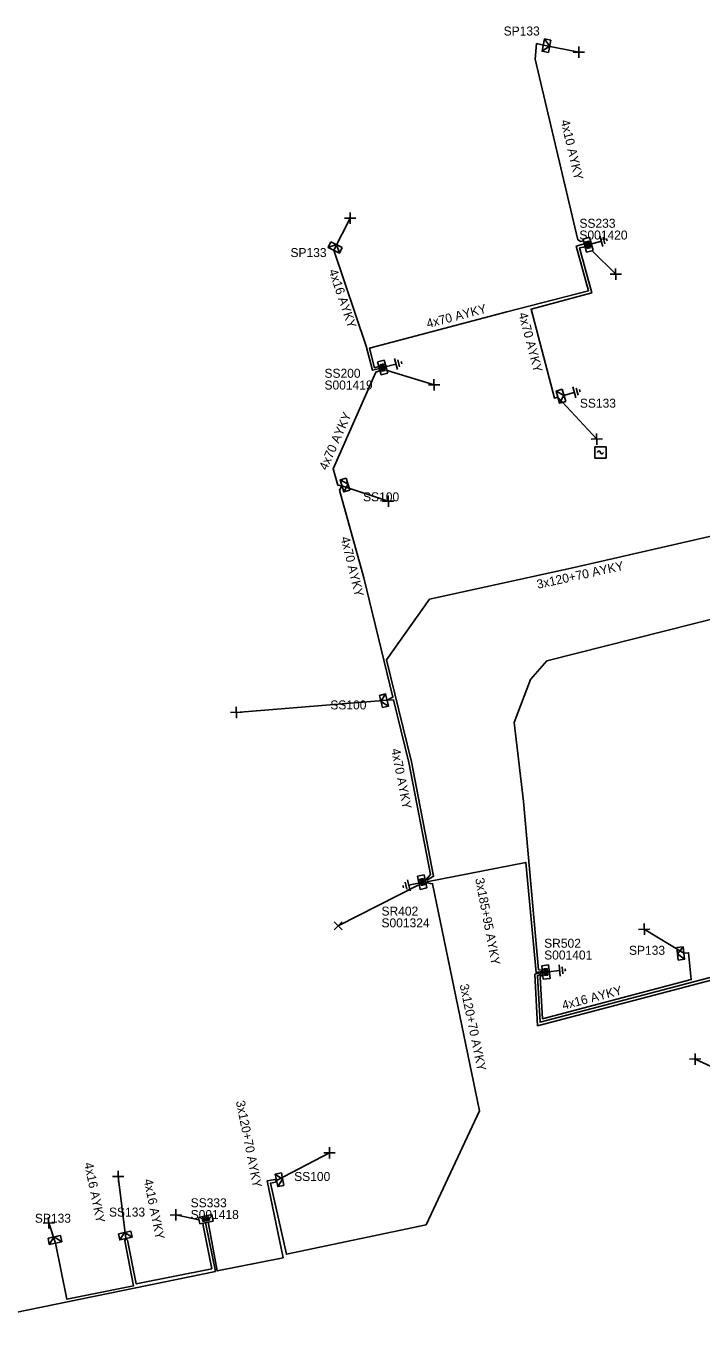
# Model space of a CAD drawing. Extents: x -762500 to -761285, y -1155006 to -1154135.
# Drawn here: x -762371 to -762296.3, y -1154695.7 to -1154549.7 of the extents above; entities that cross this region are included whole.
import ezdxf

# ---------------------------------------------------------------- set-up
doc = ezdxf.new("R2010")
doc.units = 0
for name, color, linetype in [('Vrstva 15', 7, 'Continuous'), ('Vrstva 28', 7, 'Continuous'), ('Vrstva 29', 7, 'Continuous'), ('Vrstva 30', 7, 'Continuous'), ('Vrstva 31', 7, 'Continuous'), ('Vrstva 33', 7, 'Continuous'), ('Vrstva 34', 7, 'Continuous'), ('Vrstva 5', 7, 'Continuous'), ('Vrstva 59', 7, 'Continuous'), ('Vrstva 6', 7, 'Continuous')]:
    doc.layers.add(name, color=color, linetype=linetype)

msp = doc.modelspace()

# ---------------------------------------------------------------- linework, layer by layer
at = {"layer": 'Vrstva 15'}
for points in [[(-762308.583, -1154573.801), (-762307.376, -1154573.477)], [(-762307.537, -1154572.873), (-762307.214, -1154574.081)], [(-762307.176, -1154573.026), (-762306.972, -1154573.787)], [(-762306.806, -1154573.187), (-762306.772, -1154573.315)], [(-762306.772, -1154573.315), (-762306.739, -1154573.439)], [(-762331.302, -1154587.4), (-762330.095, -1154587.076)], [(-762330.257, -1154586.472), (-762329.933, -1154587.68)], [(-762329.895, -1154586.625), (-762329.691, -1154587.386)], [(-762329.526, -1154586.786), (-762329.491, -1154586.914)], [(-762329.491, -1154586.914), (-762329.458, -1154587.038)], [(-762310.537, -1154589.614), (-762310.193, -1154590.816)], [(-762310.173, -1154589.76), (-762309.955, -1154590.517)], [(-762309.801, -1154589.915), (-762309.764, -1154590.042)], [(-762309.764, -1154590.042), (-762309.729, -1154590.166)], [(-762311.566, -1154590.559), (-762310.365, -1154590.215)], [(-762328.53, -1154645.369), (-762328.811, -1154644.151)], [(-762329.279, -1154644.9), (-762329.308, -1154644.776)], [(-762329.249, -1154645.03), (-762329.279, -1154644.9)], [(-762328.886, -1154645.204), (-762329.063, -1154644.436)], [(-762327.452, -1154644.479), (-762328.67, -1154644.76)], [(-762313.234, -1154654.338), (-762311.991, -1154654.208)], [(-762312.056, -1154653.586), (-762311.926, -1154654.829)], [(-762311.723, -1154653.794), (-762311.64, -1154654.577)], [(-762311.383, -1154654.01), (-762311.369, -1154654.142)], [(-762311.369, -1154654.142), (-762311.356, -1154654.27)]]:
    msp.add_lwpolyline(points, dxfattribs=at)
at = {"layer": 'Vrstva 28'}
for points in [[(-762308.673, -1154573.05), (-762309.398, -1154573.244)], [(-762309.398, -1154573.244), (-762309.01, -1154574.693)], [(-762308.757, -1154573.47), (-762309.122, -1154573.567)], [(-762309.122, -1154573.567), (-762308.929, -1154574.286)], [(-762308.79, -1154573.527), (-762309.064, -1154573.601)], [(-762309.064, -1154573.601), (-762308.896, -1154574.228)], [(-762308.823, -1154573.585), (-762309.006, -1154573.634)], [(-762309.006, -1154573.634), (-762308.862, -1154574.17)], [(-762308.857, -1154573.643), (-762308.948, -1154573.668)], [(-762308.948, -1154573.668), (-762308.829, -1154574.113)], [(-762308.794, -1154574.06), (-762308.892, -1154573.695)], [(-762308.738, -1154574.088), (-762308.857, -1154573.643)], [(-762308.829, -1154574.113), (-762308.738, -1154574.088)], [(-762308.68, -1154574.122), (-762308.823, -1154573.585)], [(-762308.622, -1154574.155), (-762308.79, -1154573.527)], [(-762308.564, -1154574.188), (-762308.757, -1154573.47)], [(-762308.285, -1154574.499), (-762308.673, -1154573.05)], [(-762309.01, -1154574.693), (-762308.285, -1154574.499)], [(-762308.929, -1154574.286), (-762308.564, -1154574.188)], [(-762308.896, -1154574.228), (-762308.622, -1154574.155)], [(-762308.862, -1154574.17), (-762308.68, -1154574.122)], [(-762331.41, -1154586.641), (-762332.131, -1154586.848)], [(-762332.131, -1154586.848), (-762331.718, -1154588.29)], [(-762331.486, -1154587.062), (-762331.849, -1154587.166)], [(-762331.849, -1154587.166), (-762331.644, -1154587.882)], [(-762331.518, -1154587.121), (-762331.791, -1154587.199)], [(-762331.791, -1154587.199), (-762331.612, -1154587.823)], [(-762331.551, -1154587.179), (-762331.732, -1154587.231)], [(-762331.732, -1154587.231), (-762331.579, -1154587.765)], [(-762331.398, -1154587.713), (-762331.551, -1154587.179)], [(-762331.339, -1154587.745), (-762331.518, -1154587.121)], [(-762331.281, -1154587.777), (-762331.486, -1154587.062)], [(-762330.997, -1154588.083), (-762331.41, -1154586.641)], [(-762331.718, -1154588.29), (-762330.997, -1154588.083)], [(-762331.583, -1154587.237), (-762331.674, -1154587.264)], [(-762331.674, -1154587.264), (-762331.547, -1154587.706)], [(-762331.644, -1154587.882), (-762331.281, -1154587.777)], [(-762331.513, -1154587.654), (-762331.617, -1154587.29)], [(-762331.612, -1154587.823), (-762331.339, -1154587.745)], [(-762331.456, -1154587.68), (-762331.583, -1154587.237)], [(-762331.579, -1154587.765), (-762331.398, -1154587.713)], [(-762331.547, -1154587.706), (-762331.456, -1154587.68)], [(-762326.982, -1154643.598), (-762327.715, -1154643.754)], [(-762327.715, -1154643.754), (-762327.403, -1154645.221)], [(-762327.083, -1154644), (-762327.453, -1154644.078)], [(-762327.453, -1154644.078), (-762327.298, -1154644.806)], [(-762327.12, -1154644.056), (-762327.397, -1154644.115)], [(-762327.397, -1154644.115), (-762327.262, -1154644.75)], [(-762327.156, -1154644.112), (-762327.341, -1154644.151)], [(-762327.341, -1154644.151), (-762327.226, -1154644.694)], [(-762327.193, -1154644.168), (-762327.285, -1154644.187)], [(-762327.097, -1154644.618), (-762327.193, -1154644.168)], [(-762327.041, -1154644.655), (-762327.156, -1154644.112)], [(-762326.985, -1154644.691), (-762327.12, -1154644.056)], [(-762326.929, -1154644.728), (-762327.083, -1154644)], [(-762326.67, -1154645.065), (-762326.982, -1154643.598)], [(-762327.403, -1154645.221), (-762326.67, -1154645.065)], [(-762327.298, -1154644.806), (-762326.929, -1154644.728)], [(-762327.285, -1154644.187), (-762327.189, -1154644.638)], [(-762327.262, -1154644.75), (-762326.985, -1154644.691)], [(-762327.23, -1154644.218), (-762327.152, -1154644.588)], [(-762327.226, -1154644.694), (-762327.041, -1154644.655)], [(-762327.189, -1154644.638), (-762327.097, -1154644.618)], [(-762313.206, -1154653.584), (-762313.952, -1154653.662)], [(-762313.952, -1154653.662), (-762313.795, -1154655.154)], [(-762313.354, -1154653.985), (-762313.73, -1154654.025)], [(-762313.73, -1154654.025), (-762313.652, -1154654.765)], [(-762313.396, -1154654.037), (-762313.678, -1154654.067)], [(-762313.678, -1154654.067), (-762313.61, -1154654.713)], [(-762313.438, -1154654.089), (-762313.626, -1154654.109)], [(-762313.626, -1154654.109), (-762313.568, -1154654.661)], [(-762313.48, -1154654.141), (-762313.574, -1154654.151)], [(-762313.574, -1154654.151), (-762313.526, -1154654.609)], [(-762313.483, -1154654.563), (-762313.523, -1154654.187)], [(-762313.432, -1154654.599), (-762313.48, -1154654.141)], [(-762313.38, -1154654.641), (-762313.438, -1154654.089)], [(-762313.328, -1154654.683), (-762313.396, -1154654.037)], [(-762313.276, -1154654.725), (-762313.354, -1154653.985)], [(-762313.049, -1154655.076), (-762313.206, -1154653.584)], [(-762313.795, -1154655.154), (-762313.049, -1154655.076)], [(-762313.652, -1154654.765), (-762313.276, -1154654.725)], [(-762313.61, -1154654.713), (-762313.328, -1154654.683)], [(-762313.568, -1154654.661), (-762313.38, -1154654.641)], [(-762313.526, -1154654.609), (-762313.432, -1154654.599)], [(-762350.473, -1154681.204), (-762351.941, -1154681.516)], [(-762351.941, -1154681.516), (-762351.785, -1154682.25)], [(-762351.785, -1154682.25), (-762350.317, -1154681.938)], [(-762350.798, -1154681.467), (-762351.526, -1154681.621)], [(-762351.526, -1154681.621), (-762351.447, -1154681.991)], [(-762350.834, -1154681.523), (-762351.47, -1154681.658)], [(-762351.47, -1154681.658), (-762351.411, -1154681.935)], [(-762351.447, -1154681.991), (-762350.72, -1154681.836)], [(-762350.871, -1154681.579), (-762351.414, -1154681.694)], [(-762351.414, -1154681.694), (-762351.375, -1154681.879)], [(-762351.411, -1154681.935), (-762350.776, -1154681.8)], [(-762351.375, -1154681.879), (-762350.832, -1154681.763)], [(-762350.907, -1154681.635), (-762351.358, -1154681.73)], [(-762351.358, -1154681.73), (-762351.338, -1154681.823)], [(-762351.338, -1154681.823), (-762350.888, -1154681.727)], [(-762350.938, -1154681.689), (-762351.308, -1154681.768)], [(-762350.888, -1154681.727), (-762350.907, -1154681.635)], [(-762350.832, -1154681.763), (-762350.871, -1154681.579)], [(-762350.776, -1154681.8), (-762350.834, -1154681.523)], [(-762350.72, -1154681.836), (-762350.798, -1154681.467)], [(-762350.317, -1154681.938), (-762350.473, -1154681.204)]]:
    msp.add_lwpolyline(points, dxfattribs=at)
at = {"layer": 'Vrstva 31'}
for points in [[(-762313.237, -1154552.604), (-762313.924, -1154552.47), (-762313.657, -1154551.096), (-762312.97, -1154551.23)], [(-762313.103, -1154551.917), (-762313.924, -1154552.47)], [(-762313.103, -1154551.917), (-762313.657, -1154551.096)], [(-762313.237, -1154552.604), (-762312.97, -1154551.23)], [(-762336.036, -1154574.185), (-762336.354, -1154574.809), (-762337.601, -1154574.173), (-762337.283, -1154573.549)], [(-762336.659, -1154573.867), (-762337.601, -1154574.173)], [(-762336.036, -1154574.185), (-762337.283, -1154573.549)], [(-762336.659, -1154573.867), (-762336.354, -1154574.809)], [(-762311.313, -1154591.223), (-762311.986, -1154591.416), (-762312.372, -1154590.07), (-762311.699, -1154589.877)], [(-762311.506, -1154590.55), (-762312.372, -1154590.07)], [(-762311.313, -1154591.223), (-762311.699, -1154589.877)], [(-762311.506, -1154590.55), (-762311.986, -1154591.416)], [(-762335.203, -1154601.043), (-762335.876, -1154601.236), (-762336.261, -1154599.89), (-762335.589, -1154599.697)], [(-762335.396, -1154600.37), (-762336.261, -1154599.89)], [(-762335.396, -1154600.37), (-762335.876, -1154601.236)], [(-762335.203, -1154601.043), (-762335.589, -1154599.697)], [(-762331.92, -1154623.748), (-762331.241, -1154623.578), (-762330.902, -1154624.937), (-762331.581, -1154625.106)], [(-762331.751, -1154624.427), (-762331.241, -1154623.578)], [(-762331.92, -1154623.748), (-762331.581, -1154625.106)], [(-762331.751, -1154624.427), (-762330.902, -1154624.937)], [(-762299.031, -1154651.647), (-762298.336, -1154651.562), (-762298.165, -1154652.952), (-762298.86, -1154653.037)], [(-762299.031, -1154651.647), (-762298.86, -1154653.037)], [(-762298.945, -1154652.342), (-762298.336, -1154651.562)], [(-762298.945, -1154652.342), (-762298.165, -1154652.952)], [(-762342.479, -1154677.972), (-762343.164, -1154678.117), (-762343.455, -1154676.748), (-762342.77, -1154676.602)], [(-762342.625, -1154677.287), (-762343.455, -1154676.748)], [(-762342.625, -1154677.287), (-762343.164, -1154678.117)], [(-762342.479, -1154677.972), (-762342.77, -1154676.602)], [(-762367.209, -1154683.539), (-762368.578, -1154683.83)], [(-762367.209, -1154683.539), (-762367.063, -1154684.224), (-762368.432, -1154684.515), (-762368.578, -1154683.83)], [(-762359.428, -1154683.039), (-762360.797, -1154683.33)], [(-762359.428, -1154683.039), (-762359.282, -1154683.723), (-762360.652, -1154684.014), (-762360.797, -1154683.33)], [(-762360.112, -1154683.184), (-762360.652, -1154684.014)], [(-762360.112, -1154683.184), (-762359.282, -1154683.723)], [(-762367.893, -1154683.685), (-762368.432, -1154684.515)], [(-762367.893, -1154683.685), (-762367.063, -1154684.224)]]:
    msp.add_lwpolyline(points, dxfattribs=at)
at = {"layer": 'Vrstva 34'}
for points in [[(-762309.859, -1154553.195), (-762309.881, -1154551.945)], [(-762310.495, -1154552.581), (-762309.245, -1154552.559)], [(-762335.775, -1154570.941), (-762334.525, -1154570.919)], [(-762335.139, -1154571.555), (-762335.161, -1154570.305)], [(-762305.769, -1154577.755), (-762305.791, -1154576.505)], [(-762306.405, -1154577.141), (-762305.155, -1154577.119)], [(-762326.505, -1154589.391), (-762325.255, -1154589.369)], [(-762325.869, -1154590.005), (-762325.891, -1154588.755)], [(-762308.515, -1154595.391), (-762307.265, -1154595.369)], [(-762307.879, -1154596.005), (-762307.901, -1154594.755)], [(-762306.856, -1154596.236), (-762308.106, -1154596.236)], [(-762308.106, -1154596.236), (-762308.106, -1154597.486)], [(-762307.481, -1154596.861), (-762307.482, -1154596.845), (-762307.484, -1154596.83), (-762307.488, -1154596.814), (-762307.494, -1154596.799), (-762307.501, -1154596.785), (-762307.51, -1154596.772), (-762307.52, -1154596.759), (-762307.531, -1154596.748), (-762307.543, -1154596.738), (-762307.557, -1154596.729), (-762307.571, -1154596.721), (-762307.586, -1154596.716), (-762307.601, -1154596.712), (-762307.617, -1154596.709), (-762307.633, -1154596.708), (-762307.649, -1154596.709), (-762307.665, -1154596.711), (-762307.68, -1154596.715), (-762307.695, -1154596.721), (-762307.709, -1154596.728), (-762307.723, -1154596.737), (-762307.735, -1154596.747), (-762307.747, -1154596.758), (-762307.757, -1154596.77), (-762307.766, -1154596.784), (-762307.773, -1154596.798), (-762307.779, -1154596.813), (-762307.783, -1154596.828), (-762307.785, -1154596.844), (-762307.786, -1154596.86), (-762307.786, -1154596.861)], [(-762307.481, -1154596.861), (-762307.481, -1154596.877), (-762307.478, -1154596.893), (-762307.475, -1154596.908), (-762307.469, -1154596.923), (-762307.462, -1154596.937), (-762307.454, -1154596.95), (-762307.445, -1154596.963), (-762307.434, -1154596.974), (-762307.422, -1154596.984), (-762307.409, -1154596.993), (-762307.395, -1154597), (-762307.38, -1154597.006), (-762307.365, -1154597.01), (-762307.35, -1154597.013), (-762307.334, -1154597.014), (-762307.318, -1154597.014), (-762307.303, -1154597.012), (-762307.287, -1154597.008), (-762307.273, -1154597.003), (-762307.259, -1154596.996), (-762307.245, -1154596.987), (-762307.233, -1154596.978), (-762307.222, -1154596.967), (-762307.211, -1154596.955), (-762307.203, -1154596.942), (-762307.195, -1154596.928), (-762307.189, -1154596.913), (-762307.185, -1154596.898), (-762307.182, -1154596.883), (-762307.181, -1154596.867), (-762307.181, -1154596.866)], [(-762306.856, -1154597.486), (-762306.856, -1154596.236)], [(-762308.106, -1154597.486), (-762306.856, -1154597.486)], [(-762330.929, -1154602.875), (-762330.951, -1154601.625)], [(-762331.565, -1154602.261), (-762330.315, -1154602.239)], [(-762347.739, -1154626.255), (-762347.761, -1154625.005)], [(-762348.375, -1154625.641), (-762347.125, -1154625.619)], [(-762336.942, -1154648.808), (-762336.058, -1154649.692)], [(-762336.942, -1154649.692), (-762336.058, -1154648.808)], [(-762303.255, -1154649.641), (-762302.005, -1154649.619)], [(-762302.619, -1154650.255), (-762302.641, -1154649.005)], [(-762297.625, -1154664.011), (-762296.375, -1154663.989)], [(-762296.989, -1154664.625), (-762297.011, -1154663.375)], [(-762338.065, -1154674.391), (-762336.815, -1154674.369)], [(-762337.429, -1154675.005), (-762337.451, -1154673.755)], [(-762361.435, -1154677.011), (-762360.185, -1154676.989)], [(-762360.799, -1154677.625), (-762360.821, -1154676.375)], [(-762354.429, -1154681.875), (-762354.451, -1154680.625)], [(-762369.125, -1154682.141), (-762367.875, -1154682.119)], [(-762368.489, -1154682.755), (-762368.511, -1154681.505)], [(-762355.065, -1154681.261), (-762353.815, -1154681.239)]]:
    msp.add_lwpolyline(points, dxfattribs=at)
at = {"layer": 'Vrstva 5'}
for points in [[(-762309.35, -1154573.46), (-762309.64, -1154573.51), (-762309.97, -1154573.32), (-762314.7, -1154553.35), (-762314.53, -1154551.62), (-762313.79, -1154551.78)], [(-762331.99, -1154587.36), (-762332.45, -1154587.49), (-762333.01, -1154585.32), (-762317.82, -1154581.31), (-762308.8, -1154578.99), (-762310.15, -1154574.02), (-762309.66, -1154573.89), (-762309.26, -1154573.79)], [(-762309.18, -1154574.09), (-762309.36, -1154574.13), (-762309.78, -1154574.23), (-762308.43, -1154579.2), (-762315.15, -1154581.02), (-762312.57, -1154590.85), (-762312.18, -1154590.74)], [(-762331.92, -1154587.57), (-762332.69, -1154587.76), (-762333.38, -1154585.11), (-762336.98, -1154574.49)], [(-762326.74, -1154644.11), (-762326.26, -1154643.59), (-762328.67, -1154631.19), (-762330.35, -1154624.25), (-762331.07, -1154624.27), (-762330.42, -1154623.95), (-762333.64, -1154610.73), (-762336.33, -1154601.03), (-762336.07, -1154600.56), (-762336.52, -1154600.49), (-762337.05, -1154598.68), (-762332.3, -1154587.97), (-762331.85, -1154587.81)], [(-762253.71, -1154590.64), (-762252.46, -1154595.71), (-762282.22, -1154603.15), (-762310.37, -1154609.58), (-762326.38, -1154613.11), (-762331.12, -1154619.82), (-762328.37, -1154631.12), (-762325.93, -1154643.77), (-762326.72, -1154644.24)], [(-762229.43, -1154614.78), (-762229.39, -1154614.69), (-762227.37, -1154614.23), (-762230.95, -1154599.18), (-762248.65, -1154603.59), (-762267.92, -1154608.48), (-762287.44, -1154613.36), (-762313.42, -1154619.93), (-762315.2, -1154621.99), (-762317.02, -1154626.74), (-762315.99, -1154635.5), (-762314.32, -1154654.12), (-762314.03, -1154654.16)], [(-762326.69, -1154644.37), (-762315.74, -1154642.23), (-762314.59, -1154654.42), (-762314.01, -1154654.29)], [(-762350.85, -1154682.04), (-762350.81, -1154682.22), (-762349.86, -1154687.45), (-762342.58, -1154685.99), (-762344.33, -1154677.48), (-762343.46, -1154677.32), (-762343.31, -1154677.43), (-762343.42, -1154677.61), (-762343.97, -1154677.72), (-762342.21, -1154685.6), (-762326.76, -1154682.33), (-762320.85, -1154669.72), (-762326.05, -1154644.6), (-762326.66, -1154644.49)], [(-762313.99, -1154654.55), (-762314.44, -1154654.77), (-762314.15, -1154659.92), (-762271.93, -1154648.8), (-762271.43, -1154649.23)], [(-762313.98, -1154654.68), (-762314.13, -1154654.93), (-762313.87, -1154659.54), (-762297.44, -1154655.21), (-762297.73, -1154652.24), (-762298.25, -1154652.26)], [(-762314, -1154654.42), (-762314.75, -1154654.62), (-762314.42, -1154660.31), (-762292.28, -1154654.48), (-762289.57, -1154667.11), (-762290, -1154667.2)], [(-762391.08, -1154690.18), (-762390.95, -1154690.44), (-762390.02, -1154695.71), (-762350.07, -1154687.49), (-762351.11, -1154682.27), (-762351.13, -1154682.11)], [(-762367.75, -1154684.37), (-762366.49, -1154690.58), (-762359.12, -1154689.08), (-762360.08, -1154684.11), (-762359.97, -1154683.87), (-762359.79, -1154684.05), (-762358.81, -1154688.89), (-762350.47, -1154687.2), (-762351.4, -1154682.4), (-762351.43, -1154682.17)]]:
    msp.add_lwpolyline(points, dxfattribs=at)
at = {"layer": 'Vrstva 59'}
for points in [[(-762313.79, -1154551.78), (-762309.87, -1154552.57)], [(-762336.98, -1154574.49), (-762335.15, -1154570.93)], [(-762308.4, -1154574.56), (-762305.78, -1154577.13)], [(-762331.05, -1154587.8), (-762325.88, -1154589.38)], [(-762312.18, -1154590.74), (-762307.89, -1154595.38)], [(-762336.07, -1154600.56), (-762330.94, -1154602.25)], [(-762331.07, -1154624.27), (-762347.75, -1154625.63)], [(-762327.64, -1154644.74), (-762336.5, -1154649.25)], [(-762298.25, -1154652.26), (-762302.63, -1154649.63)], [(-762290, -1154667.2), (-762297, -1154664)], [(-762343.31, -1154677.43), (-762337.44, -1154674.38)], [(-762359.97, -1154683.87), (-762360.81, -1154677)], [(-762367.75, -1154684.37), (-762368.5, -1154682.13)], [(-762351.9, -1154681.8), (-762354.44, -1154681.25)]]:
    msp.add_lwpolyline(points, dxfattribs=at)

# ---------------------------------------------------------------- texts
at = {"layer": 'Vrstva 29'}
for s, p in [('S001420', (-762309.8, -1154573.3)), ('S001419', (-762338, -1154589.9)), ('S001324', (-762331.69, -1154649.42)), ('S001401', (-762313.7, -1154652.98)), ('S001418', (-762352.8, -1154681.7))]:
    msp.add_text(s, height=0.9943, dxfattribs=at).set_placement(p)
at = {"layer": 'Vrstva 30'}
for s, p in [('SS233', (-762309.8, -1154572)), ('SS200', (-762338, -1154588.6)), ('SR402', (-762331.69, -1154648.12)), ('SR502', (-762313.7, -1154651.68)), ('SS333', (-762352.8, -1154680.4))]:
    msp.add_text(s, height=0.9943, dxfattribs=at).set_placement(p)
at = {"layer": 'Vrstva 33'}
for s, p in [('SP133', (-762318.18, -1154550.72)), ('SP133', (-762341.76, -1154575.24)), ('SS133', (-762309.75, -1154591.91)), ('SS100', (-762333.73, -1154602.27)), ('SS100', (-762337.35, -1154625.3)), ('SP133', (-762304.32, -1154652.46)), ('SS100', (-762341.35, -1154677.49)), ('SS133', (-762361.83, -1154681.43)), ('SP133', (-762370.03, -1154682.11))]:
    msp.add_text(s, height=0.9943, dxfattribs=at).set_placement(p)
at = {"layer": 'Vrstva 6'}
for s, height, rotation, p in [('4x10 AYKY', 0.9943, 283.32732, (-762311.89, -1154560.16)), ('4x16 AYKY', 0.9943, 288.71127, (-762337.55, -1154576.76)), ('4x70 AYKY', 0.9943, 14.7816, (-762326.57, -1154583.11)), ('4x70 AYKY', 0.9943, 284.74758, (-762316.55, -1154581.5)), ('4x70 AYKY', 0.9943, 66.08022, (-762337.74, -1154598.91)), ('4x70 AYKY', 0.9943, 283.66876, (-762336.21, -1154606.3)), ('3x120+70 AYKY', 0.99428, 12.44277, (-762314.4, -1154611.96)), ('4x70 AYKY', 0.9943, 280.99859, (-762330.62, -1154629.72)), ('3x185+95 AYKY', 0.99428, 280.71447, (-762321.33, -1154644.04)), ('3x120+70 AYKY', 0.99428, 281.71261, (-762323.05, -1154655.79)), ('4x16 AYKY', 0.9943, 14.74889, (-762311.58, -1154658.55)), ('3x120+70 AYKY', 0.99429, 281.32052, (-762347.8, -1154668.69)), ('4x16 AYKY', 0.9943, 281.53721, (-762364.58, -1154675.54)), ('4x16 AYKY', 0.9943, 281.42345, (-762357.99, -1154677.36))]:
    msp.add_text(s, height=height, rotation=rotation, dxfattribs=at).set_placement(p)

doc.saveas('drawing.dxf')
